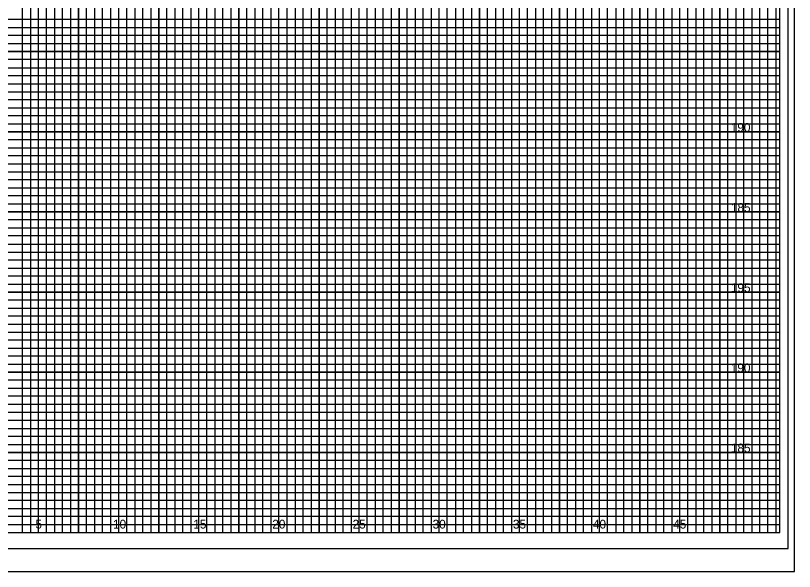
# Model space of a CAD drawing. Extents: x -4 to 103, y -2 to 138.
# Drawn here: x 54.82 to 103.4, y 68.4 to 103.08 of the extents above; entities that cross this region are included whole.
import ezdxf

# ---------------------------------------------------------------- set-up
doc = ezdxf.new("R2010")
doc.units = 0
for name, color, linetype in [('Old_Level_10', 7, 'Continuous'), ('Old_Level_16', 7, 'Continuous'), ('Old_Level_3', 7, 'Continuous'), ('Old_Level_4', 7, 'Continuous'), ('Old_Level_5', 7, 'Continuous'), ('Old_Level_8', 7, 'Continuous'), ('Prop Dimension', 7, 'Continuous'), ('Prop XS Finish Grade', 7, 'Continuous'), ('Prop XS SE Text', 7, 'Continuous')]:
    doc.layers.add(name, color=color, linetype=linetype)

msp = doc.modelspace()

# ---------------------------------------------------------------- linework, layer by layer
at = {"layer": 'Old_Level_10'}
for p, q in [((56.25, 70.825), (56.25, 135.825)), ((58.75, 70.825), (58.75, 135.825)), ((61.25, 70.825), (61.25, 135.825)), ((63.75, 70.825), (63.75, 135.825)), ((66.25, 70.825), (66.25, 135.825)), ((68.75, 70.825), (68.75, 135.825)), ((71.25, 70.825), (71.25, 135.825)), ((73.75, 70.825), (73.75, 135.825)), ((91.25, 70.825), (91.25, 134.25)), ((93.75, 70.825), (93.75, 134.25)), ((96.25, 70.825), (96.25, 134.25)), ((98.75, 70.825), (98.75, 134.25)), ((101.25, 70.825), (101.25, 134.25)), ((76.25, 70.825), (76.25, 132.825)), ((78.75, 70.825), (78.75, 132.825)), ((81.25, 70.825), (81.25, 132.825)), ((83.75, 70.825), (83.75, 132.825)), ((86.25, 70.825), (86.25, 132.825)), ((88.75, 70.825), (88.75, 132.825)), ((0, 100.825), (102.5, 100.825)), ((0, 98.325), (102.5, 98.325)), ((0, 95.825), (102.5, 95.825)), ((0, 93.325), (102.5, 93.325)), ((0, 90.825), (102.5, 90.825)), ((0, 88.325), (102.5, 88.325)), ((0, 85.825), (102.5, 85.825)), ((0, 83.325), (102.5, 83.325)), ((0, 80.825), (102.5, 80.825)), ((0, 78.325), (102.5, 78.325)), ((0, 75.825), (102.5, 75.825)), ((0, 73.325), (102.5, 73.325))]:
    msp.add_line(p, q, dxfattribs=at)
at = {"layer": 'Old_Level_3'}
msp.add_line((-3.5, 68.4), (102.1625, 68.4), dxfattribs=at)
at = {"layer": 'Old_Level_4'}
msp.add_lwpolyline([(103, 136.825), (-2.8, 136.825), (-2.8, 69.825), (103, 69.825)], close=True, dxfattribs=at)
at = {"layer": 'Old_Level_5'}
msp.add_lwpolyline([(103.4, 138.225), (-3.5, 138.225), (-3.5, 68.4), (103.4, 68.4)], close=True, dxfattribs=at)
at = {"layer": 'Old_Level_8'}
for points in [[(56.25, 70.825), (56.25, 135.825)], [(58.75, 135.825), (58.75, 70.825), (61.25, 70.825), (61.25, 135.825)], [(63.75, 135.825), (63.75, 70.825), (66.25, 70.825), (66.25, 135.825)], [(68.75, 135.825), (68.75, 70.825), (71.25, 70.825), (71.25, 135.825)], [(73.75, 135.825), (73.75, 70.825), (76.25, 70.825), (76.25, 132.825)], [(88.75, 132.825), (88.75, 70.825), (91.25, 70.825), (91.25, 134.25)], [(93.75, 134.25), (93.75, 70.825), (96.25, 70.825), (96.25, 134.25)], [(98.75, 134.25), (98.75, 70.825), (101.25, 70.825), (101.25, 134.25)], [(78.75, 132.825), (78.75, 70.825), (81.25, 70.825), (81.25, 132.825)], [(83.75, 132.825), (83.75, 70.825), (86.25, 70.825), (86.25, 132.825)], [(0, 98.325), (102.5, 98.325), (102.5, 100.825), (0, 100.825)], [(0, 93.325), (102.5, 93.325), (102.5, 95.825), (0, 95.825)], [(0, 88.325), (102.5, 88.325), (102.5, 90.825), (0, 90.825)], [(0, 83.325), (102.5, 83.325), (102.5, 85.825), (0, 85.825)], [(0, 78.325), (102.5, 78.325), (102.5, 80.825), (0, 80.825)], [(0, 73.325), (102.5, 73.325), (102.5, 75.825), (0, 75.825)]]:
    msp.add_lwpolyline(points, dxfattribs=at)
at = {"layer": 'Prop Dimension'}
for points in [[(54.75, 70.825), (55.25, 70.825), (55.25, 135.825)], [(55.75, 135.825), (55.75, 70.825), (56.75, 70.825), (56.75, 135.825)], [(57.25, 135.825), (57.25, 70.825), (57.75, 70.825), (57.75, 135.825)], [(58.25, 135.825), (58.25, 70.825), (59.25, 70.825), (59.25, 135.825)], [(59.75, 135.825), (59.75, 70.825), (60.25, 70.825), (60.25, 135.825)], [(60.75, 135.825), (60.75, 70.825), (61.75, 70.825), (61.75, 135.825)], [(62.25, 135.825), (62.25, 70.825), (62.75, 70.825), (62.75, 135.825)], [(63.25, 135.825), (63.25, 70.825), (64.25, 70.825), (64.25, 135.825)], [(64.75, 135.825), (64.75, 70.825), (65.25, 70.825), (65.25, 135.825)], [(65.75, 135.825), (65.75, 70.825), (66.75, 70.825), (66.75, 135.825)], [(67.25, 135.825), (67.25, 70.825), (67.75, 70.825), (67.75, 135.825)], [(68.25, 135.825), (68.25, 70.825), (69.25, 70.825), (69.25, 135.825)], [(69.75, 135.825), (69.75, 70.825), (70.25, 70.825), (70.25, 135.825)], [(70.75, 135.825), (70.75, 70.825), (71.75, 70.825), (71.75, 135.825)], [(72.25, 135.825), (72.25, 70.825), (72.75, 70.825), (72.75, 135.825)], [(73.25, 135.825), (73.25, 70.825), (74.25, 70.825), (74.25, 132.825)], [(89.75, 132.825), (89.75, 70.825), (90.25, 70.825), (90.25, 134.25)], [(90.75, 134.25), (90.75, 70.825), (91.75, 70.825), (91.75, 134.25)], [(92.25, 134.25), (92.25, 70.825), (92.75, 70.825), (92.75, 134.25)], [(93.25, 134.25), (93.25, 70.825), (94.25, 70.825), (94.25, 134.25)], [(94.75, 134.25), (94.75, 70.825), (95.25, 70.825), (95.25, 134.25)], [(95.75, 134.25), (95.75, 70.825), (96.75, 70.825), (96.75, 134.25)], [(97.25, 134.25), (97.25, 70.825), (97.75, 70.825), (97.75, 134.25)], [(98.25, 134.25), (98.25, 70.825), (99.25, 70.825), (99.25, 134.25)], [(99.75, 134.25), (99.75, 70.825), (100.25, 70.825), (100.25, 134.25)], [(100.25, 134.25), (100.75, 134.25), (100.75, 70.825), (101.75, 70.825), (101.75, 134.25), (102.25, 134.25), (102.25, 70.825)], [(74.75, 132.825), (74.75, 70.825), (75.25, 70.825), (75.25, 132.825)], [(75.75, 132.825), (75.75, 70.825), (76.75, 70.825), (76.75, 132.825)], [(77.25, 132.825), (77.25, 70.825), (77.75, 70.825), (77.75, 132.825)], [(78.25, 132.825), (78.25, 70.825), (79.25, 70.825), (79.25, 132.825)], [(79.75, 132.825), (79.75, 70.825), (80.25, 70.825), (80.25, 132.825)], [(80.75, 132.825), (80.75, 70.825), (81.75, 70.825), (81.75, 132.825)], [(82.25, 132.825), (82.25, 70.825), (82.75, 70.825), (82.75, 132.825)], [(83.25, 132.825), (83.25, 70.825), (84.25, 70.825), (84.25, 132.825)], [(84.75, 132.825), (84.75, 70.825), (85.25, 70.825), (85.25, 132.825)], [(85.75, 132.825), (85.75, 70.825), (86.75, 70.825), (86.75, 132.825)], [(87.25, 132.825), (87.25, 70.825), (87.75, 70.825), (87.75, 132.825)], [(88.25, 132.825), (88.25, 70.825), (89.25, 70.825), (89.25, 132.825)], [(0, 102.325), (102.5, 102.325), (102.5, 102.825), (0, 102.825)], [(0, 101.325), (102.5, 101.325), (102.5, 101.825), (0, 101.825)], [(0, 99.825), (102.5, 99.825), (102.5, 100.325), (0, 100.325)], [(0, 98.825), (102.5, 98.825), (102.5, 99.325), (0, 99.325)], [(0, 97.325), (102.5, 97.325), (102.5, 97.825), (0, 97.825)], [(0, 96.325), (102.5, 96.325), (102.5, 96.825), (0, 96.825)], [(0, 94.825), (102.5, 94.825), (102.5, 95.325), (0, 95.325)], [(0, 93.825), (102.5, 93.825), (102.5, 94.325), (0, 94.325)], [(0, 92.325), (102.5, 92.325), (102.5, 92.825), (0, 92.825)], [(0, 91.325), (102.5, 91.325), (102.5, 91.825), (0, 91.825)], [(0, 89.825), (102.5, 89.825), (102.5, 90.325), (0, 90.325)], [(0, 88.825), (102.5, 88.825), (102.5, 89.325), (0, 89.325)], [(0, 87.325), (102.5, 87.325), (102.5, 87.825), (0, 87.825)], [(0, 86.325), (102.5, 86.325), (102.5, 86.825), (0, 86.825)], [(0, 84.825), (102.5, 84.825), (102.5, 85.325), (0, 85.325)], [(0, 83.825), (102.5, 83.825), (102.5, 84.325), (0, 84.325)], [(0, 82.325), (102.5, 82.325), (102.5, 82.825), (0, 82.825)], [(0, 81.325), (102.5, 81.325), (102.5, 81.825), (0, 81.825)], [(0, 79.825), (102.5, 79.825), (102.5, 80.325), (0, 80.325)], [(0, 78.825), (102.5, 78.825), (102.5, 79.325), (0, 79.325)], [(0, 77.325), (102.5, 77.325), (102.5, 77.825), (0, 77.825)], [(0, 76.325), (102.5, 76.325), (102.5, 76.825), (0, 76.825)], [(0, 74.825), (102.5, 74.825), (102.5, 75.325), (0, 75.325)], [(0, 73.825), (102.5, 73.825), (102.5, 74.325), (0, 74.325)], [(0, 72.325), (102.5, 72.325), (102.5, 72.825), (0, 72.825)], [(0, 71.325), (102.5, 71.325), (102.5, 71.825), (0, 71.825)]]:
    msp.add_lwpolyline(points, dxfattribs=at)
at = {"layer": 'Prop XS SE Text'}
msp.add_line((-3.5, 68.4), (103.4, 68.4), dxfattribs=at)
msp.add_lwpolyline([(102.5, 135.825), (0, 135.825), (0, 70.825), (102.5, 70.825)], close=True, dxfattribs=at)

# ---------------------------------------------------------------- texts
at = {"layer": 'Old_Level_16'}
for s, p in [('5', (56.0574, 71.075)), ('10', (60.8971, 71.075)), ('15', (65.9057, 71.075)), ('20', (70.8312, 71.075)), ('25', (75.8399, 71.075)), ('30', (80.8312, 71.075)), ('35', (85.8399, 71.075)), ('40', (90.8313, 71.075)), ('45', (95.8399, 71.075))]:
    msp.add_text(s, height=0.55, dxfattribs=at).set_placement(p)
at = {"layer": 'Prop XS Finish Grade'}
for s, p in [('190', (99.4296, 95.825)), ('185', (99.4383, 90.825)), ('195', (99.4383, 85.825)), ('190', (99.4296, 80.825)), ('185', (99.4383, 75.825))]:
    msp.add_text(s, height=0.55, dxfattribs=at).set_placement(p)

doc.saveas('drawing.dxf')
